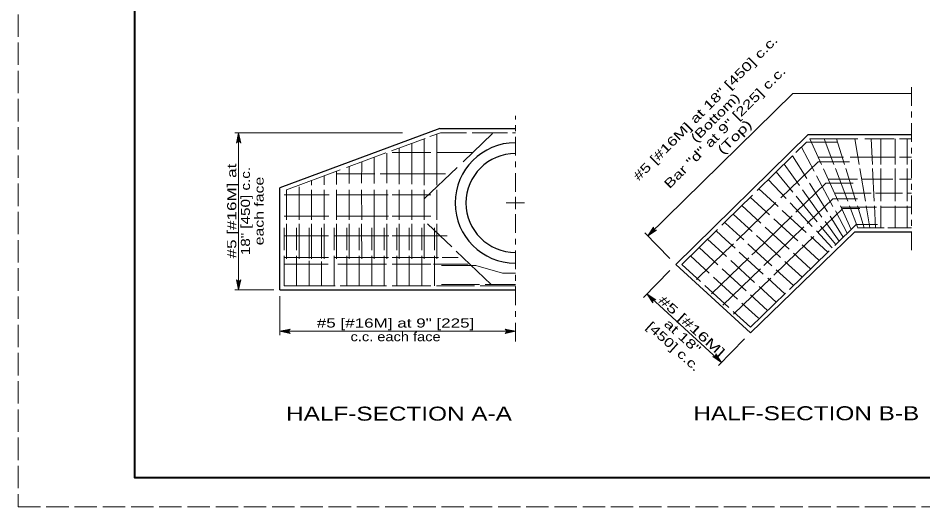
# Model space of a CAD drawing. Extents: x 1083.1 to 1117.1, y 697.4 to 743.4.
# Drawn here: x 1083.13 to 1098.64, y 721.35 to 729.74 of the extents above; entities that cross this region are included whole.
import ezdxf
from ezdxf.enums import TextEntityAlignment as Align

# ---------------------------------------------------------------- set-up
doc = ezdxf.new("R2010")
doc.units = 0
doc.header["$LTSCALE"] = 0.064
doc.linetypes.add('DOT_DASHED', pattern=[7.7, 5, -1.2, 0.3, -1.2])
doc.linetypes.add('LONG_DASHED', pattern=[7.5, 6, -1.5])
doc.layers.add('1', color=7, linetype='Continuous', lineweight=13)

msp = doc.modelspace()

# ---------------------------------------------------------------- linework, layer by layer
at = {"layer": '1', "linetype": 'DOT_DASHED'}
for p, q in [((1098.44192, 725.75492), (1098.44192, 728.59025)), ((1091.65292, 726.75983), (1091.65292, 728.06267)), ((1091.65292, 726.37325), (1091.65292, 724.15208))]:
    msp.add_line(p, q, dxfattribs=at)
at = {"layer": '1'}
for p, q in [((1093.92083, 726.00467), (1096.40658, 728.44642)), ((1096.40658, 728.44642), (1098.44192, 728.44642)), ((1089.71767, 727.77233), (1086.84117, 727.77233)), ((1086.88308, 727.61017), (1086.90783, 727.77233)), ((1086.89342, 727.61633), (1086.90783, 727.77233)), ((1086.90783, 725.07433), (1086.90783, 727.77233)), ((1086.90783, 727.61917), (1086.90783, 727.77233)), ((1086.91917, 727.6175), (1086.90783, 727.77233)), ((1086.93025, 727.61208), (1086.90783, 727.77233)), ((1090.37033, 727.77233), (1090.18592, 727.70408)), ((1090.30542, 726.8705), (1090.30542, 727.74825)), ((1090.37033, 727.77233), (1090.812, 727.77233)), ((1091.25775, 727.75575), (1090.75567, 727.27508)), ((1090.90875, 727.77233), (1091.51925, 727.77233)), ((1091.60175, 727.77233), (1091.65283, 727.77225)), ((1090.10625, 727.67467), (1089.53117, 727.46183)), ((1089.87592, 726.89208), (1089.87583, 727.58933)), ((1090.09067, 726.87408), (1090.09058, 727.66883)), ((1096.45908, 727.431), (1096.64217, 727.61058)), ((1096.64217, 727.61058), (1097.16642, 727.61058)), ((1097.52442, 727.66758), (1096.70008, 727.66767)), ((1096.9, 727.22875), (1096.70008, 727.66767)), ((1097.1135, 727.22867), (1096.94917, 727.66758)), ((1097.29483, 727.22875), (1097.15808, 727.66767)), ((1097.54533, 727.22875), (1097.471, 727.66767)), ((1098.14442, 727.66767), (1097.64375, 727.66767)), ((1097.77492, 727.22875), (1097.75508, 727.66758)), ((1097.91592, 727.22867), (1097.916, 727.66758)), ((1098.16142, 727.22867), (1098.16142, 727.66758)), ((1098.44192, 727.66758), (1098.24033, 727.66758)), ((1098.36992, 727.22875), (1098.36992, 727.66758)), ((1089.43175, 727.425), (1088.75858, 727.17592)), ((1089.4465, 726.90642), (1089.4465, 727.421)), ((1089.5375, 727.43033), (1090.20442, 727.43025)), ((1089.66117, 726.8885), (1089.66117, 727.50983)), ((1090.301, 727.43033), (1090.91775, 727.43025)), ((1096.77725, 727.10983), (1096.55583, 727.52608)), ((1089.01692, 726.90633), (1089.017, 727.2715)), ((1089.23167, 726.89925), (1089.23175, 727.351)), ((1095.79883, 726.78225), (1096.4025, 727.37533)), ((1096.84242, 727.27367), (1096.20192, 726.65333)), ((1096.64717, 726.98383), (1096.4025, 727.37533)), ((1096.84242, 727.27367), (1097.38258, 727.27367)), ((1097.277, 727.351), (1096.84433, 727.35092)), ((1097.95175, 727.35092), (1097.39483, 727.351)), ((1098.15325, 727.35092), (1097.95175, 727.35092)), ((1098.44192, 727.35092), (1098.24042, 727.35092)), ((1088.64867, 727.13517), (1087.72858, 726.79475)), ((1088.5875, 726.88483), (1088.58742, 727.11258)), ((1088.80225, 726.90283), (1088.80225, 727.192)), ((1090.65258, 727.17642), (1090.09058, 726.6385)), ((1096.40983, 726.75375), (1096.1245, 727.10233)), ((1096.524, 726.86458), (1096.2595, 727.23483)), ((1097.18808, 726.59608), (1096.93425, 727.15358)), ((1097.35017, 726.59608), (1097.14058, 727.15642)), ((1097.49208, 726.596), (1097.31742, 727.15642)), ((1097.6525, 726.59608), (1097.55767, 727.15642)), ((1097.80342, 726.59608), (1097.77808, 727.15642)), ((1097.916, 726.596), (1097.916, 727.15642)), ((1098.16133, 726.59608), (1098.16133, 727.15642)), ((1098.36992, 726.596), (1098.36992, 727.15642)), ((1088.15808, 726.8705), (1088.15808, 726.95367)), ((1088.37283, 726.87767), (1088.37283, 727.03317)), ((1088.5875, 727.06725), (1089.24358, 727.06725)), ((1089.33308, 727.06733), (1090.00008, 727.06725)), ((1090.00342, 727.06725), (1090.45175, 727.06725)), ((1096.29442, 726.642), (1095.98658, 726.96983)), ((1097.09742, 726.50817), (1096.81733, 727.03467)), ((1097.52042, 726.97717), (1097.01467, 726.97717)), ((1097.92442, 726.97717), (1097.58792, 726.97717)), ((1098.12592, 726.97717), (1097.92442, 726.97717)), ((1098.44192, 726.97717), (1098.24042, 726.97717)), ((1087.72858, 726.28), (1087.72858, 726.79475)), ((1087.94333, 726.28), (1087.94333, 726.84533)), ((1088.15808, 726.28008), (1088.15808, 726.79467)), ((1088.37283, 726.28008), (1088.37283, 726.79475)), ((1088.5875, 726.28008), (1088.5875, 726.79475)), ((1088.80217, 726.28), (1088.80217, 726.79475)), ((1089.017, 726.28008), (1089.01692, 726.79475)), ((1089.23167, 726.28008), (1089.23175, 726.79475)), ((1089.44642, 726.28008), (1089.44642, 726.79475)), ((1089.66117, 726.28008), (1089.66117, 726.79467)), ((1089.87592, 726.28), (1089.87592, 726.79475)), ((1090.09067, 726.28), (1090.09067, 726.79467)), ((1090.30542, 726.28008), (1090.30542, 726.79467)), ((1096.15742, 726.505), (1095.826, 726.809)), ((1096.97492, 726.906), (1096.46283, 726.41008)), ((1096.90917, 726.32575), (1096.577, 726.79058)), ((1097.00183, 726.41567), (1096.69367, 726.90908)), ((1096.97492, 726.906), (1097.44608, 726.90592)), ((1087.68675, 726.70425), (1088.46217, 726.70425)), ((1088.5875, 726.70417), (1089.47292, 726.70425)), ((1089.53758, 726.70417), (1090.20433, 726.70425)), ((1091.65292, 726.67075), (1091.65292, 726.46233)), ((1095.2565, 726.24958), (1095.71583, 726.70083)), ((1096.00975, 726.36217), (1095.6795, 726.66525)), ((1096.82617, 726.24542), (1096.46933, 726.68125)), ((1097.09708, 726.63942), (1096.656, 726.21217)), ((1097.09708, 726.63942), (1097.5205, 726.63942)), ((1097.75083, 726.73708), (1097.12383, 726.73708)), ((1098.21067, 726.73708), (1097.82525, 726.737)), ((1098.28975, 726.737), (1098.21067, 726.73708)), ((1098.44192, 726.73708), (1098.36283, 726.73708)), ((1091.81133, 726.56642), (1091.4945, 726.5665)), ((1096.11808, 726.57217), (1095.44275, 725.91842)), ((1095.86233, 726.21925), (1095.53308, 726.52133)), ((1096.7425, 726.16433), (1096.36092, 726.57117)), ((1097.40908, 726.11067), (1097.22483, 726.51517)), ((1097.63467, 726.49625), (1097.23358, 726.49625)), ((1097.5215, 726.13858), (1097.3805, 726.51508)), ((1097.63467, 726.1385), (1097.51733, 726.51517)), ((1097.84375, 726.49625), (1097.63467, 726.49625)), ((1097.73008, 726.1385), (1097.66625, 726.51517)), ((1097.824, 726.13858), (1097.807, 726.51517)), ((1097.916, 726.13858), (1097.916, 726.51508)), ((1098.44192, 726.49625), (1097.91625, 726.49625)), ((1098.16133, 726.13817), (1098.16133, 726.51517)), ((1098.36992, 726.1385), (1098.36992, 726.51517)), ((1087.68675, 726.34117), (1088.45142, 726.34125)), ((1088.5875, 726.34125), (1089.4765, 726.34125)), ((1089.53758, 726.34117), (1090.20442, 726.34125)), ((1095.71467, 726.07642), (1095.38667, 726.37733)), ((1096.64, 726.06233), (1096.229, 726.43933)), ((1097.26383, 726.47225), (1096.83658, 726.0585)), ((1097.274, 725.97983), (1097.05008, 726.33833)), ((1097.34308, 726.04658), (1097.1395, 726.42917)), ((1097.26383, 726.47225), (1097.55742, 726.47217)), ((1087.72858, 725.60875), (1087.72858, 726.20975)), ((1087.94325, 725.60875), (1087.94333, 726.20983)), ((1088.15808, 725.60875), (1088.15808, 726.20983)), ((1088.37275, 725.60875), (1088.37275, 726.20983)), ((1088.58742, 725.60875), (1088.5875, 726.20983)), ((1088.80225, 725.60875), (1088.80225, 726.20983)), ((1089.017, 725.60867), (1089.01692, 726.20983)), ((1089.23175, 725.67892), (1089.23167, 726.28008)), ((1089.23175, 725.60867), (1089.23167, 726.20983)), ((1089.44642, 725.60867), (1089.4465, 726.20975)), ((1089.66117, 725.60875), (1089.66117, 726.20975)), ((1089.87592, 725.60875), (1089.87592, 726.20975)), ((1090.09058, 725.60867), (1090.09067, 726.20983)), ((1090.56025, 725.81292), (1090.1485, 726.20708)), ((1090.30542, 725.60875), (1090.30542, 726.20983)), ((1095.18975, 726.184), (1095.2565, 726.24958)), ((1096.4925, 725.91933), (1096.0815, 726.29633)), ((1097.14542, 725.85533), (1096.88625, 726.17183)), ((1097.20458, 725.91242), (1096.96325, 726.25008)), ((1097.49683, 726.19542), (1097.12725, 725.83767)), ((1087.68675, 725.75867), (1087.68675, 726.141)), ((1087.90133, 725.75867), (1087.90133, 726.141)), ((1088.11608, 725.61425), (1088.11617, 726.14092)), ((1088.33092, 725.61417), (1088.33092, 726.14092)), ((1088.54567, 725.75858), (1088.54567, 726.141)), ((1088.76042, 725.75867), (1088.76042, 726.14092)), ((1088.97508, 725.75867), (1088.975, 726.14092)), ((1089.18983, 725.75858), (1089.18983, 726.141)), ((1089.4045, 725.75858), (1089.40458, 726.141)), ((1089.61933, 725.75867), (1089.61925, 726.141)), ((1089.83392, 725.75867), (1089.834, 726.141)), ((1090.04867, 725.75867), (1090.04867, 726.141)), ((1090.2635, 725.75867), (1090.2635, 726.14092)), ((1094.3025, 725.61625), (1093.87267, 726.05383)), ((1094.01975, 726.13275), (1093.92083, 726.00467)), ((1094.02358, 726.12108), (1093.92083, 726.00467)), ((1094.03033, 726.11175), (1093.92083, 726.00467)), ((1094.04242, 726.1035), (1093.92083, 726.00467)), ((1094.05408, 726.10033), (1093.92083, 726.00467)), ((1094.50775, 725.514), (1095.11908, 726.11467)), ((1096.09792, 725.72483), (1095.78642, 726.01058)), ((1096.34475, 725.77658), (1095.93392, 726.15358)), ((1097.08558, 725.79892), (1096.81367, 726.08875)), ((1097.63467, 726.1385), (1097.51558, 726.1385)), ((1097.97308, 726.13858), (1097.63467, 726.1385)), ((1098.44192, 726.13858), (1098.04067, 726.13858)), ((1087.68667, 726.00125), (1088.44783, 726.00117)), ((1088.54558, 726.00117), (1089.48008, 726.00117)), ((1089.5375, 726.00125), (1090.48292, 726.00125)), ((1095.27183, 725.64767), (1094.94708, 725.94567)), ((1095.7945, 725.72483), (1095.63867, 725.86767)), ((1097.00783, 725.72475), (1096.71667, 725.992)), ((1091.236, 725.16608), (1090.636, 725.74042)), ((1095.12417, 725.50475), (1094.80067, 725.80175)), ((1095.90208, 725.34783), (1095.49108, 725.72483)), ((1096.04967, 725.49067), (1095.7945, 725.72483)), ((1096.19717, 725.63358), (1096.09792, 725.72483)), ((1096.71417, 725.43758), (1096.4215, 725.70633)), ((1096.70442, 725.72475), (1096.569, 725.84908)), ((1096.86175, 725.5805), (1096.70442, 725.72475)), ((1097.00942, 725.72342), (1097.00783, 725.72475)), ((1087.68675, 725.14525), (1087.68667, 725.6585)), ((1087.68667, 725.63083), (1088.44783, 725.63075)), ((1087.90142, 725.14517), (1087.90133, 725.6585)), ((1088.11617, 725.14525), (1088.11617, 725.57467)), ((1088.33092, 725.14525), (1088.33083, 725.56508)), ((1088.54558, 725.14525), (1088.54567, 725.65842)), ((1088.54825, 725.63083), (1089.47642, 725.63083)), ((1088.76033, 725.14525), (1088.76042, 725.6585)), ((1088.97508, 725.14525), (1088.97508, 725.6585)), ((1089.18975, 725.14525), (1089.18983, 725.6585)), ((1089.40458, 725.14517), (1089.4045, 725.65842)), ((1089.53758, 725.63075), (1090.33592, 725.63075)), ((1089.61933, 725.14525), (1089.61933, 725.6585)), ((1089.834, 725.14517), (1089.83392, 725.6585)), ((1090.04875, 725.14517), (1090.04867, 725.6585)), ((1090.2635, 725.14525), (1090.2635, 725.65842)), ((1090.39725, 725.63083), (1090.66867, 725.63075)), ((1094.97667, 725.36183), (1094.65417, 725.65783)), ((1095.65442, 725.6275), (1095.01658, 725.00992)), ((1095.75442, 725.205), (1095.3435, 725.58192)), ((1096.56658, 725.29475), (1096.27392, 725.56342)), ((1087.68675, 725.51533), (1088.44067, 725.51533)), ((1088.60908, 725.51525), (1089.44492, 725.51533)), ((1089.5375, 725.51533), (1090.20442, 725.51533)), ((1090.24817, 725.51533), (1090.84025, 725.51533)), ((1090.38433, 725.49442), (1090.976, 725.49442)), ((1090.976, 725.49442), (1091.43417, 725.36283)), ((1094.3025, 725.40825), (1093.84617, 724.94375)), ((1094.82908, 725.219), (1094.50775, 725.514)), ((1095.60683, 725.06208), (1095.19583, 725.43908)), ((1095.85742, 725.43908), (1095.20967, 724.81192)), ((1096.419, 725.15183), (1096.12625, 725.42042)), ((1086.88542, 725.23458), (1086.90783, 725.07433)), ((1086.93258, 725.23642), (1086.90783, 725.07433)), ((1091.43417, 725.36283), (1091.65292, 725.36283)), ((1095.45925, 724.91917), (1095.04833, 725.29617)), ((1096.03192, 725.2795), (1095.39042, 724.65833)), ((1096.27133, 725.009), (1095.97867, 725.27742)), ((1086.8965, 725.22908), (1086.90783, 725.07433)), ((1086.92225, 725.23033), (1086.90783, 725.07433)), ((1086.90783, 725.2275), (1086.90783, 725.07433)), ((1087.68675, 725.14525), (1088.56067, 725.14517)), ((1088.64725, 725.14525), (1089.445, 725.14525)), ((1089.53758, 725.14517), (1090.20433, 725.14525)), ((1090.30108, 725.14525), (1090.95375, 725.14525)), ((1090.38433, 725.16608), (1091.03708, 725.16608)), ((1091.05025, 725.14525), (1091.65283, 725.14525)), ((1091.1335, 725.16608), (1091.65292, 725.16608)), ((1095.31158, 724.77625), (1094.90083, 725.15325)), ((1096.12383, 724.86608), (1095.83108, 725.13467)), ((1087.51175, 725.07433), (1086.84117, 725.07433)), ((1087.61583, 724.97017), (1087.61583, 724.29942)), ((1094.01933, 724.898), (1093.91008, 725.00533)), ((1094.01125, 724.88575), (1093.91008, 725.00533)), ((1094.00833, 724.874), (1093.91008, 725.00533)), ((1094.02842, 724.90492), (1093.91008, 725.00533)), ((1094.04008, 724.909), (1093.91008, 725.00533)), ((1095.1885, 723.83233), (1093.91008, 725.00533)), ((1096.283, 725.02033), (1095.681, 724.43742)), ((1095.97617, 724.72308), (1095.68342, 724.99167)), ((1095.81958, 724.5885), (1095.53592, 724.84875)), ((1095.681, 724.43742), (1095.38833, 724.706)), ((1087.77608, 724.38875), (1087.61583, 724.36633)), ((1087.77067, 724.37767), (1087.61583, 724.36633)), ((1087.61583, 724.36633), (1091.65292, 724.36633)), ((1087.769, 724.36633), (1087.61583, 724.36633)), ((1087.77183, 724.35192), (1087.61583, 724.36633)), ((1087.778, 724.3415), (1087.61583, 724.36633)), ((1091.49083, 724.3415), (1091.65292, 724.36633)), ((1091.49267, 724.38875), (1091.65292, 724.36633)), ((1091.49692, 724.35192), (1091.65292, 724.36633)), ((1091.49817, 724.37767), (1091.65292, 724.36633)), ((1091.49975, 724.36633), (1091.65292, 724.36633)), ((1095.58008, 724.23608), (1095.13375, 723.78175)), ((1095.05842, 723.92867), (1095.1885, 723.83233)), ((1095.07008, 723.93275), (1095.1885, 723.83233)), ((1095.07917, 723.93967), (1095.1885, 723.83233)), ((1095.08725, 723.95192), (1095.1885, 723.83233)), ((1095.09017, 723.96367), (1095.1885, 723.83233))]:
    msp.add_line(p, q, dxfattribs=at)
at = {"layer": '1', "lineweight": 25}
for p, q in [((1090.35742, 727.84308), (1087.61583, 726.82858)), ((1090.35742, 727.84308), (1091.65292, 727.84317)), ((1094.40475, 725.51225), (1096.67108, 727.73842)), ((1087.61583, 725.07433), (1087.61583, 726.82858)), ((1097.63475, 726.06767), (1097.46667, 726.06758)), ((1098.44192, 726.06767), (1097.63475, 726.06767)), ((1095.68233, 724.34008), (1094.40475, 725.51225)), ((1087.61583, 725.07433), (1091.65292, 725.07442))]:
    msp.add_line(p, q, dxfattribs=at)
at = {"layer": '1', "linetype": 'LONG_DASHED'}
msp.add_lwpolyline([(1083.12642, 721.35408), (1117.12642, 721.35408), (1117.12642, 743.35408), (1083.12642, 743.35408)], close=True, dxfattribs=at)
at = {"layer": '1', "lineweight": 25}
msp.add_lwpolyline([(1085.12642, 742.85408), (1116.62642, 742.85408), (1116.62642, 721.85408), (1085.12642, 721.85408)], close=True, dxfattribs=at)
at = {"layer": '1', "lineweight": 40}
msp.add_lwpolyline([(1085.12642, 742.85408), (1116.62642, 742.85408), (1116.62642, 721.85408), (1085.12642, 721.85408)], close=True, dxfattribs=at)
msp.add_lwpolyline([(1085.12642, 742.85408), (1116.62642, 742.85408), (1116.62642, 721.85408), (1085.12642, 721.85408)], close=True, dxfattribs=at)
at = {"layer": '1'}
for points in [[(1086.87242, 727.59533), (1086.90783, 727.77233), (1086.94325, 727.59533)], [(1096.39992, 726.34908), (1095.75508, 725.72475), (1095.70567, 725.67717)], [(1095.567, 725.9335), (1095.2565, 726.2185), (1095.24017, 726.2335)], [(1097.49683, 726.19542), (1097.63475, 726.1955), (1097.86275, 726.1955)], [(1094.07217, 726.10317), (1093.92083, 726.00467), (1094.02267, 726.15375)], [(1095.4195, 725.7905), (1095.25642, 725.94008), (1095.09358, 726.08958)], [(1096.59808, 726.15583), (1096.15267, 725.72483), (1095.9125, 725.49242)], [(1095.38958, 725.86683), (1095.2565, 725.73808), (1094.75558, 725.25325)], [(1096.76842, 725.9925), (1096.49208, 725.72483), (1096.08517, 725.33092)], [(1097.03167, 725.74492), (1097.01083, 725.72475), (1096.35033, 725.0855)], [(1086.94325, 725.25133), (1086.90783, 725.07433), (1086.87242, 725.25133)], [(1094.0115, 724.856), (1093.91008, 725.00533), (1094.06117, 724.9065)], [(1087.79283, 724.33092), (1087.61583, 724.36633), (1087.79283, 724.40167)], [(1091.47592, 724.33092), (1091.65292, 724.36633), (1091.47592, 724.40167)], [(1095.087, 723.98167), (1095.1885, 723.83233), (1095.03742, 723.93117)]]:
    msp.add_lwpolyline(points, dxfattribs=at)
at = {"layer": '1', "lineweight": 25}
for points in [[(1096.67108, 727.73842), (1097.63475, 727.73842), (1098.44192, 727.7385)], [(1097.46667, 726.06758), (1097.11267, 725.72483), (1095.68233, 724.34008)]]:
    msp.add_lwpolyline(points, dxfattribs=at)
at = {"layer": '1'}
for centre, start, end in [((1086.90787, 727.58103), 22.08782, 157.91395), ((1094.05759, 726.13847), 156.44518, 292.27131), ((1086.90779, 725.2656), 202.08782, 337.91395), ((1094.04655, 724.87127), 67.59915, 203.42527), ((1087.80714, 724.36634), 112.08782, 247.91395), ((1091.46165, 724.36634), 292.08605, 67.91218), ((1095.05197, 723.96639), 247.59915, 23.42527)]:
    msp.add_arc(centre, 0.0382, start, end, dxfattribs=at)
at = {"layer": '1', "lineweight": 25}
for major_axis in [(1.0331, 0), (0.84802, 0)]:
    msp.add_ellipse((1091.6529, 726.5665), major_axis=major_axis, ratio=0.999895, start_param=1.57079633, end_param=4.71238898, dxfattribs=at)

# ---------------------------------------------------------------- texts
at = {"layer": '1'}
for s, rotation, width, p in [('#5 [#16M] at 18" [450] c.c.', 45.116, 1.4, (1094.96606, 728.141)), ('Bar "d" at 9" [225] c.c.', 45.116, 1.4, (1095.2986, 727.80967)), ('(Bottom)', 45.116, 1.35, (1095.13237, 727.97537)), ('(Top)', 45.116, 1.45, (1095.46487, 727.64412)), ('#5 [#16M] at', 90, 1.4, (1086.86708, 726.42867)), ('18" [450] c.c.', 90, 1.25, (1087.10175, 726.42871)), ('each face', 90, 1.3, (1087.33642, 726.42863)), ('#5 [#16M]', 317.927, 1.55, (1094.62357, 724.39701)), ('[450] c.c.', 317.927, 1.35, (1094.30907, 724.04856)), ('at 18"', 317.927, 1.4, (1094.46636, 724.22274))]:
    msp.add_text(s, height=0.156, rotation=rotation, dxfattribs=dict(at, width=width)).set_placement(p, align=Align.CENTER)
for s, width, p in [('#5 [#16M] at 9" [225]', 1.4, (1089.59804, 724.43017)), ('c.c. each face', 1.2, (1089.59808, 724.1955))]:
    msp.add_text(s, height=0.156, dxfattribs=dict(at, width=width)).set_placement(p, align=Align.CENTER)
at = {"layer": '1', "width": 1.3}
for s, p in [('HALF-SECTION A-A', (1087.7215, 722.83358)), ('HALF-SECTION B-B', (1094.70425, 722.84025))]:
    msp.add_text(s, height=0.24, dxfattribs=at).set_placement(p)

doc.saveas('drawing.dxf')
